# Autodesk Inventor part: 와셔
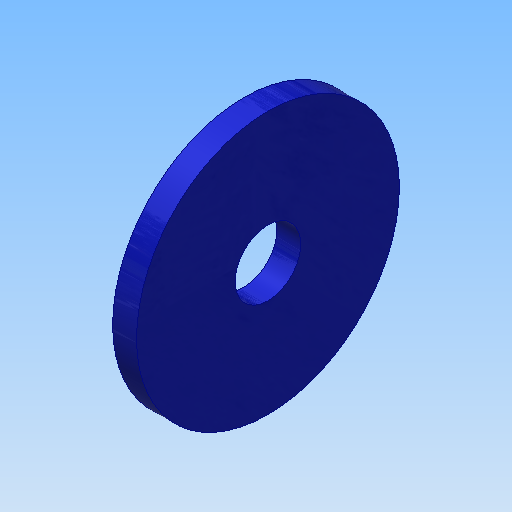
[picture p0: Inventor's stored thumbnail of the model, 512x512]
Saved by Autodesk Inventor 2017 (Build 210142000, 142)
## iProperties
Created: 2015-12
Part Number: 와셔
Material: 스테인리스강
Document SubType Name: Modeling
Designer: mduedu
Density: 8.08 g/cm^3
Mass: 6.77437 g
Surface Area: 10.3005 cm^2
Volume: 0.838413 cm^3
Appearance: 파란색 - 벽 페인트 - 광택
Author: mduedu
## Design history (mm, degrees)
sketch "스케치1"
  geometry: C1 r 2.75 at (0, 0); C2 r 11 at (0, 0); 1 further point
  constraints: 2 centre point, 2 coincident
  dimensions: "d0" = 5.5 diameter of C1; "d1" = 22 diameter of C2
extrude "돌출1" new body sketch "스케치1" stored distance "d2" = 2; taper "d3" = 0 deg
node "솔리드1"
